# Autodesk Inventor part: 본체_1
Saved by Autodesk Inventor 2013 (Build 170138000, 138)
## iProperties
Created: 2016-12
Part Number: 본체_1
Material: 일반
Document SubType Name: Modeling
Designer: Administrator
Density: 1 g/cm^3
Author: Administrator
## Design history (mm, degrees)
derived "본체.ipt"
feature "본체::본체.ipt" dims "d0" = 10
tag "피쳐 태그1"
node "솔리드1"
